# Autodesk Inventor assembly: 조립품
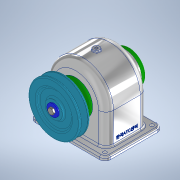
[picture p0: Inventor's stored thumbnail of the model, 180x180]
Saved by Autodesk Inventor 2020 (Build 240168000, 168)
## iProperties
Created: 2022-09
Part Number: 조립품
Document SubType Name: Assembly
Designer: Administrator
Author: Administrator
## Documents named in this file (16)
- C:\Users\Administrator\Desktop\720906V1019\조립품.iam
- C:\Users\Administrator\Desktop\720906V1019\본체.ipt
- C:\Users\Administrator\Desktop\720906V1019\축.ipt
- C:\Users\Administrator\Desktop\720906V1019\키 6 x 6 x 22.ipt
- C:\Users\Administrator\Desktop\720906V1019\스퍼기어.ipt
- C:\Users\Administrator\Desktop\720906V1019\칼라.ipt
- C:\Users\Administrator\Desktop\720906V1019\베어링 6203.ipt
- C:\Users\Administrator\Desktop\720906V1019\뒤커버.ipt
- C:\Users\Administrator\Desktop\720906V1019\앞커버.ipt
- C:\Users\Administrator\Desktop\720906V1019\오일 실 17 x 30 x 8.ipt
- C:\Users\Administrator\Desktop\720906V1019\볼트 M3 x 10.ipt
- C:\Users\Administrator\Desktop\720906V1019\키 5 x 5 x 18.ipt
- C:\Users\Administrator\Desktop\720906V1019\V-벨트풀리.ipt
- C:\Users\Administrator\Desktop\720906V1019\멈춤나사 M4 x 10.ipt
- C:\Users\Administrator\Desktop\720906V1019\와셔 6 x 22.ipt
- C:\Users\Administrator\Desktop\720906V1019\육각머리볼트 M3 x 8.ipt
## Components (9 placed, 2 different names)
1. V-벨트풀리:1
2. ISO 4762 M3 x 10:2
3. ISO 4762 M3 x 10:1
4. ISO 4762 M3 x 10:3
5. ISO 4762 M3 x 10:4
6. ISO 4762 M3 x 10:5
7. ISO 4762 M3 x 10:6
8. ISO 4762 M3 x 10:7
9. ISO 4762 M3 x 10:8
